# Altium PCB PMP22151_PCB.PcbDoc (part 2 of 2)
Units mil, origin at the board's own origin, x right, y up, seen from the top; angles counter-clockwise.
Board outline 3750 x 2000 mil, 2 copper layers (Top Layer, Bottom Layer), stack 62 mil thick; 80 components, 41 nets, 202 pads, 89 vias.
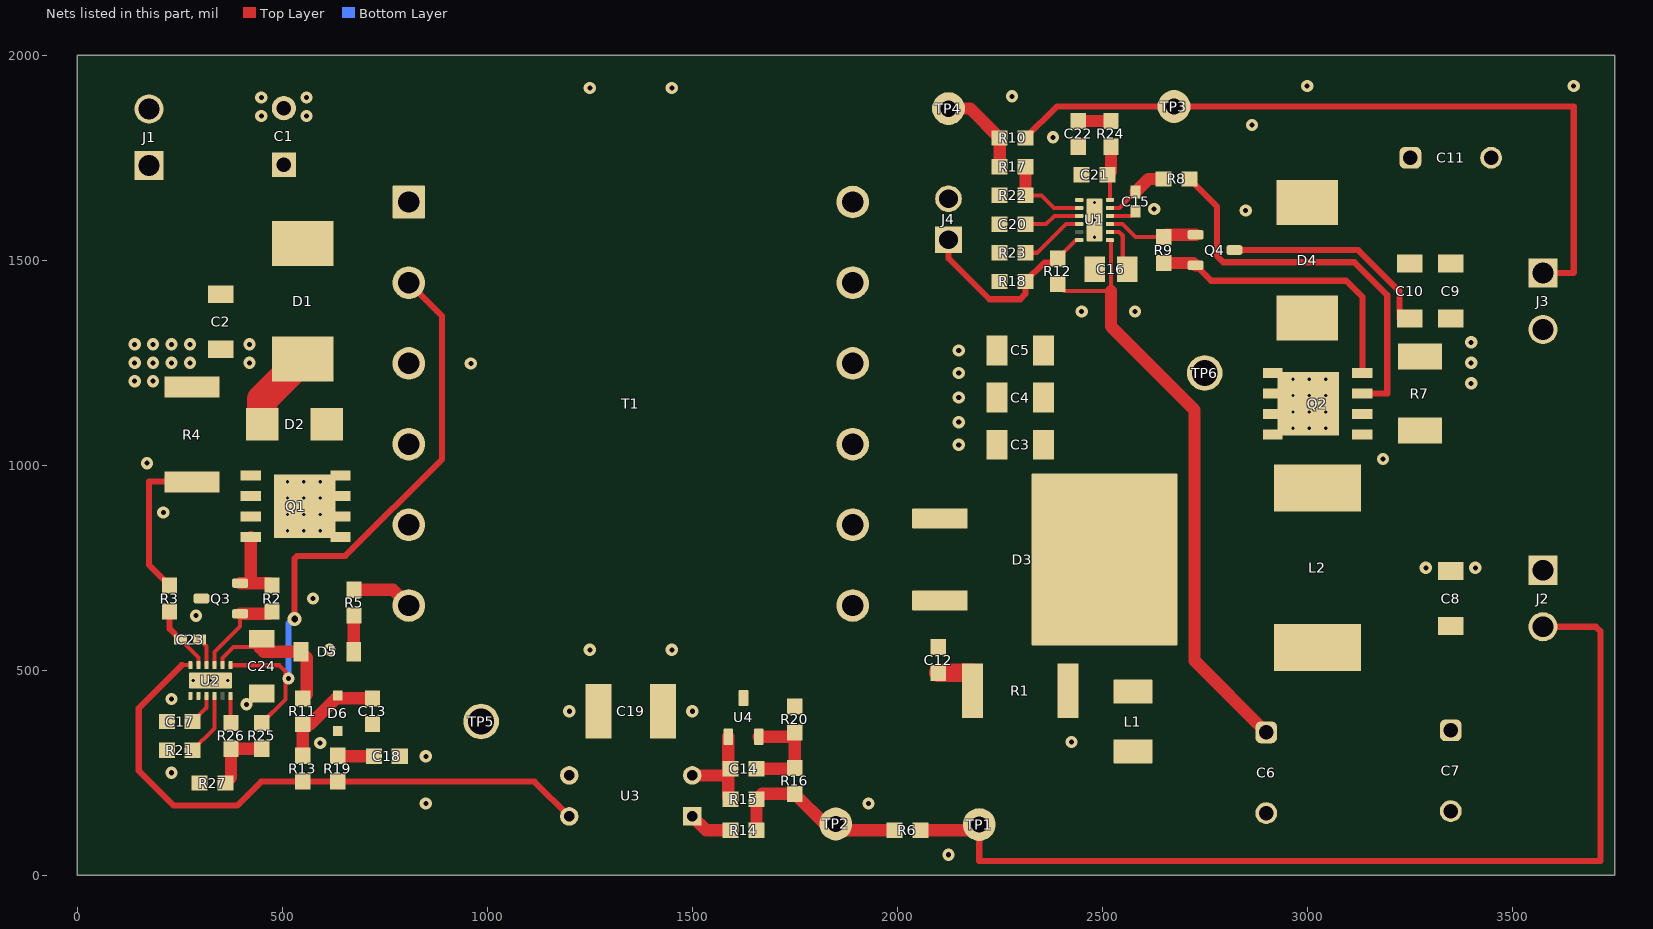
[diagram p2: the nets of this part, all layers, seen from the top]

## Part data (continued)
T1: library part CMP-0087767-1, "TRANSFORMER", Manufacturer=Wurth
TP1 TP3: library part CMP-0055137-1, "Test Point, Miniature, Red, TH", Color=Red, Manufacturer=Keystone, Supplier Part Number 1=36-5000-ND
TP2 TP4: library part CMP-0055141-1, "Test Point, Miniature, Yellow, TH", Color=Yellow, Manufacturer=Keystone, Supplier Part Number 1=36-5004-ND
TP5 TP6: library part CMP-0055148-1, "Test Point, Multipurpose, Black, TH", Color=Black, Manufacturer=Keystone, Supplier Part Number 1=36-5011-ND
U1 U2: library part CMP-0085414-1, "2.2-MHz Wide Input Nonsynchronous Boost, Sepic, Flyback Controller, DSS0012B (WSON-12)", Alternate Manufacturer="Texas Instruments", Alternate PartNumber=LM5155DSSR
U3: library part CMP-0083653-1, "Optocoupler, 5.3 kV, 100-200% CTR, SMT", Manufacturer=Vishay-Semiconductor, Supplier Part Number 1=VO618A-3-ND, Voltage_Isolation_Vrms=5.3kV
U4: library part CMP-0084732-1, "High Bandwidth Low-Iq Programmable Shunt Regulator, DBZ0003A (SOT-23-3)", Alternate Manufacturer="Texas Instruments"

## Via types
v1: diameter 29.92, hole 12.2, Top Layer to Bottom Layer, 50 vias
v2: diameter 19.68, hole 7.87, Top Layer to Bottom Layer, 30 vias
v3: diameter 29.92, hole 12.2, Top Layer to Bottom Layer, tented both sides, 8 vias
v4: diameter 34, hole 16, Top Layer to Bottom Layer, tented both sides, 1 vias

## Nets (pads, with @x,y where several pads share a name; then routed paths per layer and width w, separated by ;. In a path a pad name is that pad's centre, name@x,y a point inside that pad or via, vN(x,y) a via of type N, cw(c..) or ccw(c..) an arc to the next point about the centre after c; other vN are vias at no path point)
28V: C6.1 C7.1 C8.1 J2.2 L1.2 L2.1 R6.2 R12.2 TP1.1 U1.1 | length 3953
  Top Layer w10: R12.2@2391.3,1441.73 2408.03,1425 2521.3,1425 2521.3,1546.42 U1.1@2518.7,1549.02
  Top Layer w15: TP1.1@2200,123.74 2200,35 3715,35 3715,595 3703.9,606.1 J2.2@3575,606.1
  Top Layer w30: R6.2@2056.5,110 2186.26,110 TP1.1@2200,123.74 ; 2521.3,1425 2521.3,1338.7 2725,1135 2725,523.43 C6.1@2900,348.43
37V: C9.1 C10.1 C11.1 D4.1 J3.1 R10.2 TP3.1 | length 1849.5
  Top Layer w15: R10.2@2312.8,1798.23 2389.57,1875 TP3.1@2675,1875 3650,1875 3650,1470 3648.9,1468.9 J3.1@3575,1468.9
NetC3_1: C3.1 C4.1 C5.1 D3.2 L1.1 R1.2
NetC12_1: C12.1 R1.1 | length 127.4
  Top Layer w45: C12.1@2100,493.5 2183.86,493.5 R1.1@2183.86,450
NetC12_2: C12.2 D3.1 D3.3 T1.7 T1.8 T1.9
NetC13_2: C13.2 D6.1 R11.1 R13.2 | length 273.1
  Top Layer w30: R13.2@550,291.5 R11.1@550,368.5 568.5,368.5 631.5,431.5 C13.2@720,431.5
NetC14_1: C14.1 R16.1 R20.2 U4.2 | length 273.2
  Top Layer w30: C14.1@1656.5,260 1748.5,260 R16.1@1750,261.5 R20.2@1750,348.5 1739.25,337.76 U4.2@1662.4,337.76
NetC14_2: C14.2 R15.1 U3.2 U4.1 | length 244.2
  Top Layer w30: U3.2@1500,243.43 1584.17,243.43 1587.6,240 ; U4.1@1587.6,337.76 1587.6,240 ; R15.1@1593.5,185 1587.6,190.91 1587.6,240
NetC15_1: C15.1 R8.1 U1.5 | length 160.3
  Top Layer w10: U1.5@2518.7,1627.76 2542.2,1627.76 C15.1@2581.3,1666.85
  Top Layer w30: C15.1@2581.3,1666.85 2612.68,1698.23 R8.1@2649.8,1698.23
NetC16_1: C16.1 U1.2 | length 121.4
  Top Layer w10: U1.2@2518.7,1568.7 2541.3,1568.7 2550,1560 2550,1489.53 C16.1@2561.3,1478.23
NetC17_2: C17.2 U2.9 | length 76.5
  Top Layer w10: C17.2@281.5,375 315.16,408.66 U2.9@315.16,437.6
NetC18_2: C18.2 R19.1 | length 89.1
  Top Layer w30: R19.1@635,291.5 636.5,290 C18.2@723.5,290
NetC20_1: C20.1 U1.9 | length 139.3
  Top Layer w10: C20.1@2312.8,1588.23 2363.23,1588.23 2383.07,1608.07 U1.9@2443.9,1608.07
NetC21_1: C21.1 R24.2 U1.6 | length 135.3
  Top Layer w10: C21.1@2512.8,1708.23 2518.7,1702.32 U1.6@2518.7,1647.44
  Top Layer w30: C21.1@2512.8,1708.23 2521.3,1716.73 R24.2@2521.3,1776.73
NetC22_1: C22.1 R24.1 | length 80
  Top Layer w30: C22.1@2441.3,1839.72 R24.1@2521.3,1839.72
NetC23_1: C23.1 R3.1 U2.5 | length 160.3
  Top Layer w10: C23.1@251.38,575 295.47,530.91 U2.5@295.47,512.4
  Top Layer w15: R3.1@225,643.5 225,601.38 C23.1@251.38,575
NetD1_2: D1.2 D2.1 | length 200.4
  Top Layer w75: D2.1@451.26,1100 451.26,1160.77 D1.2@550,1259.51
NetD2_2: D2.2 Q1.5 Q1.6 Q1.7 Q1.8 Q1.9 T1.3 T1.4
  other v2: 512.5,840 552.5,840 592.5,840 512.5,880 552.5,880 592.5,880 512.5,920 552.5,920 592.5,920 512.5,960 552.5,960 592.5,960
NetD4_2: D4.2 L2.2 Q2.5 Q2.6 Q2.7 Q2.8 Q2.9
  other v2: 2965,1090 3005,1090 3045,1090 2965,1130 3005,1130 3045,1130 2965,1170 3005,1170 3045,1170 2965,1210 3005,1210 3045,1210
NetD5_2: D5.2 R5.1 | length 88.7
  Top Layer w30: D5.2@674.47,545 674.47,632.97 R5.1@675,633.5
NetJ4_1: J4.1 R12.1 R18.2 U1.12 | length 482.8
  Top Layer w10: R12.1@2391.3,1504.72 2435.59,1549.02 U1.12@2443.9,1549.02
  Top Layer w15: J4.1@2125,1550 2125,1505 2225,1405 2300,1405 2312.8,1417.8 R18.2@2312.8,1448.23 2359.45,1494.88 2381.46,1494.88 R12.1@2391.3,1504.72
NetQ1_1: Q1.1 Q1.2 Q1.3 R3.2 R4.2 | length 379.7
  Top Layer w15: R3.2@225,706.5 175,756.5 175,960 278.86,960 R4.2@280,958.86
NetQ1_4: Q1.4 Q3.2 R2.2 | length 193.6
  Top Layer w30: Q3.2@397.24,712.4 425,712.4 ; Q1.4@423,825 423,714.4 425,712.4 ; R2.2@475,706.5 469.09,712.4 425,712.4
NetQ2_1: Q2.1 Q2.2 Q2.3 R7.2 R8.2 | length 970.9
  Top Layer w15: R8.2@2712.8,1698.23 2780,1631.02 2780,1510 2795,1495 3115,1495 3195,1415 3195,1175 Q2.3@3134.5,1175
NetQ2_4: Q2.4 Q4.2 R9.2 | length 704.4
  Top Layer w15: Q4.2@2727.76,1487.6 2765.35,1450 3095,1450 3134.5,1410.5 Q2.4@3134.5,1225
  Top Layer w30: R9.2@2650,1493.5 2721.85,1493.5 Q4.2@2727.76,1487.6
NetQ3_1: Q3.1 R2.1 U2.3 | length 231.2
  Top Layer w10: U2.3@334.84,512.4 334.84,544.84 397.24,607.24 Q3.1@397.24,637.6
  Top Layer w30: Q3.1@397.24,637.6 469.09,637.6 R2.1@475,643.5
NetQ4_1: Q4.1 R9.1 U1.3 | length 224.7
  Top Layer w10: U1.3@2518.7,1588.39 2549.41,1588.39 2581.3,1556.5 R9.1@2650,1556.5
  Top Layer w30: R9.1@2650,1556.5 2655.91,1562.4 Q4.1@2727.76,1562.4
NetR5_2: R5.2 T1.6 | length 149.7
  Top Layer w30: R5.2@675,696.5 770.04,696.5 T1.6@808.66,657.87
NetR6_1: R6.1 R14.2 R15.2 R16.2 TP2.1 | length 454.3
  Top Layer w30: R14.2@1656.5,110 R15.2@1656.5,185 1670,198.5 R16.2@1750,198.5 1823.5,125 TP2.1@1850,125 1865,110 R6.1@1993.5,110
NetR10_1: R10.1 R17.2 TP4.1 | length 224.5
  Top Layer w30: TP4.1@2125,1870 2178.03,1870 R10.1@2249.8,1798.23 R17.2@2249.8,1728.23
NetR13_1: R13.1 R19.2 U2.6 U3.4 | length 1466.4
  Top Layer w10: 255,512.4 U2.6@275.79,512.4
  Top Layer w15: 255,512.4 150,407.4 150,255 235,170 390,170 448.5,228.5 R13.1@550,228.5 R19.2@635,228.5 1114.93,228.5 U3.4@1200,143.43
NetR14_1: R14.1 U3.1 | length 107.4
  Top Layer w30: U3.1@1500,143.43 1533.43,110 R14.1@1593.5,110
NetR17_1: R17.1 R22.2 U1.8 | length 213.7
  Top Layer w10: R22.2@2312.8,1658.23 2351.77,1658.23 2382.24,1627.76 U1.8@2443.9,1627.76
  Top Layer w30: R22.2@2312.8,1658.23 R17.1@2312.8,1728.23
NetR21_1: R21.1 U2.10 | length 154.7
  Top Layer w10: R21.1@281.5,305 334.84,358.35 U2.10@334.84,437.6
NetR23_2: R23.2 U1.10 | length 160.2
  Top Layer w10: R23.2@2312.8,1518.23 2341.25,1518.23 2411.41,1588.39 U1.10@2443.9,1588.39
NetR25_1: R25.1 R26.1 R27.2 | length 164.1
  Top Layer w30: R27.2@361.5,225 375,238.5 R26.1@375,308.5 R25.1@450,308.5
NetR26_2: R26.2 U2.12 | length 66.4
  Top Layer w10: U2.12@374.21,437.6 374.21,372.28 R26.2@375,371.5
PGND: C1.2 C2.2 C13.1 C17.1 C18.1 C19.2 C23.2 C24.2 D6.2 J1.2 Q3.3 R4.1 R21.2 R27.1 T1.5 TP5.1 U2.4 U2.7 U2.8 U2.13 U3.3 | length 69.4
  Top Layer w10: C23.2@298.62,575 315.16,558.46 U2.4@315.16,512.4
  other v1: 850,175 850,290 1200,400 615,550 1250,550 289.45,632.97 575,675 210,885 170,1005 140,1205 960,1248.43 140,1250 185,1250 230,1250 275,1250 140,1295 185,1295 230,1295 275,1295 449,1852 559,1852 449,1897 559,1897 1250,1920
  other v2: 282.68,475 325,475 367.32,475
  other v3: 230,250 592.56,322.7 413,417 230,430 185,1205 420.08,1250 420.08,1295
SGND: C3.2 C4.2 C5.2 C6.2 C7.2 C8.2 C9.2 C10.2 C11.2 C15.2 C16.2 C19.1 C20.2 C21.2 C22.2 J2.1 J3.2 J4.2 Q4.3 R7.1 R18.1 R20.1 R22.1 R23.1 T1.10 T1.11 T1.12 TP6.1 U1.4 U1.7 U1.13 U4.3 | length 578.5
  Top Layer w10: U1.4@2518.7,1608.07 2569.76,1608.07 C15.2@2581.3,1619.61
  Top Layer w15: Q4.3@2822.24,1525 3125,1525 3225,1425 C10.2@3225,1358.07
  other v1: 2125,50 1930,175 2425,325 1500,400 1450,550 3289.37,750 3410,750 3185,1015 2150,1050 2150,1105 2150,1165 3400,1200 2150,1225 3400,1250 2150,1280 3400,1300 2450,1375 2580,1375 2850,1621.57 2626.59,1625.2 2380,1800 2865,1830 2280,1900 1450,1920 3000,1925 3650,1925
  other v2: 2481.3,1555.91 2481.3,1598.23 2481.3,1640.55
VCC: C24.1 D5.1 R11.2 U2.2 | length 347.7
  Top Layer w10: U2.2@354.53,512.4 354.53,529.53 381.5,556.5 C24.1@443.5,556.5
  Top Layer w30: C24.1@443.5,556.5 455,545 D5.1@545.53,545 560,530.53 560,441.5 R11.2@550,431.5
Vin: C1.1 C2.1 D1.1 J1.1 R25.2 T1.1 T1.2 U2.1 | length 1514.4
  Top Layer w10: U2.1@374.21,512.4 374.21,512.13 492.87,512.13 507.5,497.5 507.5,429 R25.2@450,371.5
  Top Layer w15: v4(530,625) 530,772.2 536.63,778.83 653.83,778.83 890,1015 890,1363.94 T1.2@808.66,1445.28
  Bottom Layer w15: v3(515,480) 515,613.37 526.63,625 v4(530,625)
pads on no net: U1.11 U2.11

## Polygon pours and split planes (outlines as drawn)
NetD2_2 on Top Layer "TOP_LAYER_NETD2_2_P002" (solid, remove dead copper, pour order 2): 475,810 475,980 565,1070 565,1325 875,1325 875,950 805,950 665,810
SGND on Top Layer "TOP_LAYER_SGND_P026" (solid, remove dead copper, pour order 26): 1400,0 1400,2000 3750,2000 3750,0
37V on Top Layer "TOP_LAYER_37V_P024" (solid, remove dead copper, pour order 24): 2900,1549.02 2900.98,1550 3130,1550 3255,1425 3625,1425 3625,1850 2900,1850
NetD4_2 on Top Layer "TOP_LAYER_NETD4_2_P022" (solid, remove dead copper, pour order 22): 3150,875 2875,875 2875,1425 3090,1425 3090,1050 3150,1050
NetQ2_1 on Top Layer "TOP_LAYER_NETQ2_1_P020" (solid, remove dead copper, pour order 20): 3100,1200 3350,1200 3350,1050 3100,1050
28V on Top Layer "TOP_LAYER_28V_P018" (solid, remove dead copper, pour order 18): 2475,200 3625,200 3625,675 2475,675
NetC3_1 on Top Layer "TOP_LAYER_NETC3_1_P016" (solid, remove dead copper, pour order 16): 2325,1325 2325,375 2700,375 2700,1125 2500,1325
NetC12_2 on Top Layer "TOP_LAYER_NETC12_2_P014" (solid, remove dead copper, pour order 14): 1840,1100 1840,635 1937.29,537.71 2200,537.71 2200,870 1970,1100
PGND on Top Layer "TOP_LAYER_PGND_P006" (solid, remove dead copper, pour order 6): 1300,0 1300,2000 0,2000 0,0
Vin on Top Layer "TOP_LAYER_VIN_P004" (solid, remove dead copper, pour order 4): 125,1800 950,1800 950,1325 125,1325
NetQ1_1 on Top Layer "TOP_LAYER_NETQ1_1_P000" (solid, remove dead copper, pour order 0): 455,1050 455,855 280,855 205,930 205,1050
SGND on Bottom Layer "BOTTOM_LAYER_SGND_P012" (solid, remove dead copper, pour order 12): 1400,0 1400,2000 3750,2000 3750,0
PGND on Bottom Layer "BOTTOM_LAYER_PGND_P010" (solid, remove dead copper, pour order 10): 1300,0 1300,2000 0,2000 0,0

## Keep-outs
Keep-Out Layer:
  text ".Layer_Name" at 577,-858.49 h60

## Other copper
Top Layer:
  region net NetR13_1: 255,520 276,520 276,503 237,503
  text ".Layer_Name" at 577,-858.49 h60
Bottom Layer:
  text ".Layer_Name" at 577,-858.49 h60

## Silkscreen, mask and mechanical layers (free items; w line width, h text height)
Top Overlay:
  lines w10: 2785,475 2815,475 ; 2800,460 2800,490 ; 3085,1775 3115,1775 ; 3100,1760 3100,1790 ; 3235,475 3265,475 ; 3250,460 3250,490 ; 100,455 180,455 180,520 100,520 100,455 ; 1825,355 1825,420 1905,420 1905,355 1825,355 ; 2625,1355 2625,1420 2705,1420 2705,1355 2625,1355
  text "'.PRJ_Number'.PCB_Rev" at 70,80 h108.27
  text ".Layer_Name" at 577,-858.49 h60
Bottom Overlay:
  text ".Layer_Name" at 577,-858.49 h60
Top Paste:
  text ".Layer_Name" at 577,-858.49 h60
Bottom Paste:
  text ".Layer_Name" at 577,-858.49 h60
Top Solder:
  text ".Layer_Name" at 577,-858.49 h60
  text ".Layer_Name" at 577,-858.49 h60
Bottom Solder:
  text ".Layer_Name" at 577,-858.49 h60
Drill Guide:
  text ".Layer_Name" at 577,-858.49 h60
M1 Board Outline:
  the board outline again, w10
  text ".Layer_Name" at 577,-858.49 h60
M2 Board Dimensions:
  rectangle: 0,-275 125,-150
  rectangle: 125,-400 500,-275
  lines w7: 0,-275 1000,-275 ; 125,-400 125,-150 ; 250,-400 250,-150 ; 500,-400 500,-150 ; 750,-400 750,-150 ; 0,-400 1000,-400 1000,-150 0,-150 0,-400
  text ".Layer_Name" at 577,-858.49 h60
M3 3D STEP Top:
  text ".Layer_Name" at 577,-858.49 h60
M4 3D STEP Bottom:
  text ".Layer_Name" at 577,-858.49 h60
M5 Assembly Top:
  lines w10: -292,-930.17 6308,-930.17 ; -292,-726.83 6310,-726.83 ; -292,-523.5 -292,-1133.5 3713,-1133.5 6310,-1133.5 6310,-523.5 -291.5,-523.5 -291.5,-1133.5 1284,-1133.5 ; 2173,-1133.5 2173,-523.5 ; 3440,-726.83 3440,-523.5 ; 4280,-726.83 4280,-523.5 ; 4902,-1140 4902,-937.17
  text "COMPONENTS MARKED 'DNP' SHOULD NOT BE POPULATED." at 1153.5,-318.5 h60
  text "ASSEMBLY VARIANT:" at 1153,-434 h60
  text ".VariantName" at 2189,-434 h60
  text "PCB VIEWED FROM TOP SIDE" at -228.5,-655.67 h60
  text "BOARD #:" at 2248,-655.67 h60
  text ".PRJ_Number" at 2793.5,-655.67 h60
  text "REV:" at 3638,-655.67 h60
  text ".PCB_Rev" at 3929.5,-655.67 h60
  text "SVN REV:" at 4476,-655.67 h60
  text ".VersionControl_RevNumber" at 4982,-655.67 h60
  text "TID #:" at 2248,-859 h60
  text ".TID" at 2793.5,-859 h60
  text "PLOT NAME =" at -228.5,-1064.34 h60
  text ".plot_File_Name" at 577,-1064.34 h60
  text "GENERATED    :" at 2250,-1064.34 h60
  text ".Print_Date" at 3119.5,-1064.34 h60
  text ".Print_Time" at 3848.5,-1064.34 h60
  text "TEXAS INSTRUMENTS" at 5113,-1064.34 h60
M6 Assembly Bottom:
  lines w10: -292.5,-727.33 6309.5,-727.33 ; -290.5,-930.67 6309.5,-930.67 ; 1115.5,-1140.5 1115.5,-937.67 ; 1737.5,-727.33 1737.5,-524 ; 2577.5,-727.33 2577.5,-524 ; 3844.5,-1134 3844.5,-524 ; 4733.5,-1134 6309,-1134 6309,-524 -292.5,-524 -292.5,-1134 2304.5,-1134 6309.5,-1134 6309.5,-524
  text "COMPONENTS MARKED 'DNP' SHOULD NOT BE POPULATED." at 6102,-318 h60
  text ".VariantName" at 5058,-434 h60
  text "ASSEMBLY VARIANT:" at 6097,-434 h60
  text ".VersionControl_RevNumber" at 1035.5,-656.17 h60
  text "SVN REV:" at 1541.5,-656.17 h60
  text ".PCB_Rev" at 2088,-656.17 h60
  text "REV:" at 2379.5,-656.17 h60
  text ".PRJ_Number" at 3224,-656.17 h60
  text "BOARD #:" at 3769.5,-656.17 h60
  text "PCB VIEWED FROM BOTTOM SIDE" at 6246,-656.17 h60
  text ".TID" at 3224,-859.5 h60
  text "TID #:" at 3769.5,-859.5 h60
  text "TEXAS INSTRUMENTS" at 904.5,-1064.84 h60
  text ".Print_Time" at 2169,-1064.84 h60
  text ".Print_Date" at 2898,-1064.84 h60
  text "GENERATED    :" at 3767.5,-1064.84 h60
  text ".plot_File_Name" at 5440.5,-1064.84 h60
  text "PLOT NAME =" at 6246,-1064.84 h60
M9 Title Sheet:
  drawing of 57 lines, arcs and shapes, not listed
  text "1" at 739.84,8036.5 h70
  text "2" at 3235.5,8036.5 h70
  text "3" at 5724.84,8036.5 h70
  text "4" at 8231.51,8036.5 h70
  text "5" at 10730.5,8036.5 h70
  text "6" at 13235.5,8036.5 h70
  text "A" at -416.5,6893.5 h70
  text "A" at 14383.5,6893.5 h70
  text "B" at -416.5,4513.5 h70
  text "B" at 14383.5,4513.5 h70
  text "C" at -416.5,2138.5 h70
  text "C" at 14383.5,2138.5 h70
  text "PROJECT TITLE:" at 11343.5,277.5 h45
  text ".PRJ_Title" at 11393.5,144.17 h70
  text "DESIGNED FOR:" at 11343.5,-23.5 h45
  text ".PRJ_Customer" at 11393.5,-163.5 h70
  text "D" at -416.5,-231.5 h70
  text "D" at 14383.5,-231.5 h70
  text "FILE NAME:" at 11343.5,-323.5 h45
  text ".PCB_File_Name_No_Path" at 11393.5,-443.5 h70
  text "Texas Instruments (TI) and/or its licensors do not warrant the accuracy or completeness of this specification" at 6374,-605.34 h45
  text "ENGINEER:" at 11343.5,-613.5 h45
  text "LAYOUT BY:" at 12848.5,-613.5 h45
  text "or any information contained therein. TI and/or its licensors do not warrant that this design will meet" at 6329.01,-718 h45
  text ".PRJ_Engineer" at 11393.5,-768.49 h70
  text ".PCB_Layout" at 12899,-768.49 h70
  text "the specifications, will be suitable for your application or fit for any particular purpose, or will operate in" at 6329.01,-830.67 h45
  text ".Layer_Name" at 577,-858.49 h60
  text "ALTIUM DESIGNER VERSION:" at 12848.5,-923.5 h45
  text "an implementation. TI and/or its licensors do not warrant that the design is production worthy. You should" at 6329.01,-943.33 h45
  text "completely validate and test your design implementation to confirm the system functionality for your application." at 6374,-1056 h45
  text ".print_Scale" at 11393.5,-1056.83 h70
  text ".Application_BuildNumber" at 12899,-1056.83 h70
  text "1" at 739.84,-1263.5 h70
  text "2" at 3235.5,-1263.5 h70
  text "3" at 5724.84,-1263.5 h70
  text "4" at 8231.51,-1263.5 h70
  text "5" at 10730.5,-1263.5 h70
  text "6" at 13235.5,-1263.5 h70
M10 Fab Notes:
  drawing of 189 lines, arcs and shapes, not listed
  text "DESIGN INFORMATION" at 12382.02,6356.17 h60
  text "MIN. TRACK WIDTH:" at 11737.46,6224.05 h60
  text "8" at 12833.7,6224.05 h60
  text "MIL" at 12988.46,6224.05 h60
  text "MIN. CLEARANCE:" at 11737.46,6099.92 h60
  text "0.2" at 12773.7,6099.93 h60
  text "mm" at 12988.46,6099.92 h60
  text "MIN. VIA PAD SIZE:" at 11737.46,5975.8 h60
  text "24" at 12803.71,5975.8 h60
  text "MIL" at 12988.46,5975.8 h60
  text "0.05mm (2MIL)" at 12432.46,5845.9 h60
  text "MINIMUM ANNULAR RING" at 11408.23,5837.67 h60
  text "EXTERNAL" at 13140.46,5837.67 h60
  text "PER" at 11608.23,5727.55 h60
  text "IPC-D-275 CLASS 2 LEVEL C" at 11828.23,5727.54 h60
  text "MIL, HOLES" at 13316.46,5627.07 h60
  text "+/-" at 12924,5618.48 h60
  text "+/-" at 13778,5618.48 h60
  text "REGISTRATION TOLERANCES:" at 11408.23,5617.42 h60
  text "METAL" at 12608,5617.42 h60
  text "5" at 13184.2,5617.42 h60
  text "3" at 14017.2,5617.42 h60
  text "MIL" at 14133.46,5617.42 h60
  text "HOLE SIZE TOLERANCE (UNLESS OTHERWISE SPECIFIED):" at 11408.23,5519.1 h60
  text "+/-" at 13778,5516.23 h60
  text "3" at 14017.2,5515.17 h60
  text "MIL" at 14133.46,5515.17 h60
  text "MATERIAL:" at 11333.46,5377.52 h60
  text "FR-4 High Tg" at 12319.9,5249 h60
  text "X" at 12175.46,5241.01 h60
  text "FR-408" at 11754.46,5236.49 h60
  text "OTHER" at 13242.46,5236.49 h60
  text "62 MIL (1.6mm) +/-10%" at 12074.56,5093.46 h60
  text "X" at 11954.46,5091.01 h60
  text "THICKNESS:" at 11408.23,5085.24 h60
  text "OTHER" at 13359.46,5085.24 h60
  text "TOLERANCE:" at 11408.23,4946.92 h60
  text "X" at 12256.46,4946.92 h60
  text "ANSI IPC-6012 TYPE 3 CLASS 2" at 12434.48,4946.92 h60
  text "OTHER +/-" at 12434.46,4802.73 h60
  text "BOW & TWIST:" at 11408.23,4657.54 h60
  text "X" at 12256.46,4657.54 h60
  text "ANSI IPC-6012 TYPE 3 CLASS 2" at 12434.48,4657.54 h60
  text "OTHER +/-" at 12434.46,4510.85 h60
  text "DRILLING:" at 11333.46,4380.23 h60
  text "NC_DRILL FILES" at 13094.46,4275.04 h60
  text "REFERENCE:" at 11408.23,4271.1 h60
  text "X" at 12065.46,4271.01 h60
  text "AS SHOWN" at 12243.46,4271.1 h60
  text "X" at 12966.46,4271.1 h60
  text "OTHER" at 13392.46,4128.85 h60
  text "PTH COPPER THICKNESS:" at 11407.91,4125.32 h60
  text "X" at 12547.14,4125.32 h60
  text "20-30 um" at 12675.14,4125.32 h60
  text "BOARD FINISH:" at 11333.46,3977.73 h60
  text "SILKSCREEN:" at 11488.68,3867.6 h60
  text "X" at 12446.46,3867.6 h60
  text "TOP" at 12563.46,3867.6 h60
  text "X" at 12956.46,3867.6 h60
  text "BOTTOM" at 13074.46,3867.6 h60
  text "SILKSCREEN COLOR:" at 11488.68,3712.41 h60
  text "X" at 12445.46,3712.41 h60
  text "WHITE" at 12563.46,3712.41 h60
  text "OTHER" at 13074.46,3712.41 h60
  text "X" at 12576.46,3568.96 h60
  text "GREEN" at 12694.46,3568.96 h60
  text "OTHER" at 13312.46,3568.96 h60
  text "SOLDER RESIST COLOR:" at 11488.68,3562.1 h60
  text "X" at 12576.46,3414.71 h60
  text "MATTE" at 12694.46,3414.71 h60
  text "SEMI-GLOSS" at 13312,3414.07 h60
  text "IMMERSION GOLD (ENIG)" at 12394.46,3241.94 h60
  text "ENEPIG" at 13732,3234.72 h60
  text "SURFACE FINISH:" at 11333.46,3233.72 h60
  text "X" at 12216.46,3233.72 h60
  text "IMM. TIN/SILVER OR EQUIV" at 11663,3096.4 h60
  text "OTHER" at 13094.46,3092.47 h60
  text "ARRAY/PANEL:" at 11333.46,2937.09 h60
  text "CUT AND TRIM PER M1 BOARD OUTLINE" at 12394.46,2928.87 h60
  text "N.C. ROUTE" at 12394.46,2792.9 h60
  text "X" at 13082.46,2792.9 h60
  text "V. SCORE" at 13260.46,2792.9 h60
  text "CERTIFICATION:" at 11333.46,2663.77 h60
  text "MATERIALS AND WORKMANSHIP FOR ALL PCBS" at 12058.46,2663.77 h60
  text "TO MEET OR EXCEED THE REQUIREMENTS OF:" at 12058.46,2569.71 h60
  text "X" at 11695.97,2441.08 h60
  text "ANSI IPC-A-600F CLASS ->" at 11823.96,2441.08 h60
  text "X" at 13471.97,2441.08 h60
  text "2" at 13581.96,2441.08 h60
  text "1" at 13266.96,2439.58 h60
  text "3" at 13935.96,2439.58 h60
  text "X" at 12507.97,2293.39 h60
  text "RoHS" at 12635.96,2293.39 h60
  text "OTHER" at 13280.36,2293.39 h60
  text "PER ORDER" at 13677.42,2293.39 h60
  text "ALL BOARDS MUST MEET OR EXCEED UL94-V0 REQUIREMENTS." at 11361,2139.57 h60
  text "PCB MUST BEAR THE UL94V-0 UL REGISTERED MATERIAL ID NUMBER" at 11361,2023.5 h60
  text "ADDITIONAL REQUIREMENTS:" at 11333.46,1854.08 h60
  text "MICROSECTION:" at 11408.23,1746.95 h60
  text "YES" at 12313.96,1746.95 h60
  text "REQUIRED" at 13175.46,1602.62 h60
  text "BARE BOARD ELEC. TEST:" at 11408.23,1599.76 h60
  text "NONE" at 12713.96,1599.76 h60
  text "X" at 13057.46,1599.76 h60
  text "PER ORDER" at 13767.46,1599.76 h60
  text "XX MIL VIAS REQUIRE NON-CONDUCTIVE FILL AND PLANARIZE" at 11576.38,1394.82 h59
  text "XX MIL VIAS REQUIRE CONDUCTIVE FILL AND PLANARIZE" at 11584.38,1290.84 h60
  text "OUTER XX MIL TRACES REQUIRE 50 OHM SINGLE-ENDED IMPEDANCE" at 11583.39,1127.46 h58
  text "LAYER 2 & 3 (INNER LAYERS) XX MIL WIDE, XX MIL SPACE / TRACES REQUIRE 100 OHM DIFFERENTIAL IMPEDANCE" at 11575.39,891.74 h60
  text ".Layer_Name" at 577,-858.49 h60
M11 Gerber Information:
  lines w10: -292,-930.17 6308,-930.17 ; -292,-726.83 6310,-726.83 ; -292,-523.5 -292,-1133.5 3713,-1133.5 6310,-1133.5 6310,-523.5 -291.5,-523.5 -291.5,-1133.5 1284,-1133.5 ; 2173,-1133.5 2173,-523.5 ; 3440,-726.83 3440,-523.5 ; 4280,-726.83 4280,-523.5 ; 4902,-1140 4902,-937.17
  text "ALL ARTWORK VIEWED FROM TOP SIDE" at -228.5,-655.67 h60
  text "BOARD #:" at 2248,-655.67 h60
  text ".PRJ_Number" at 2793.5,-655.67 h60
  text "REV:" at 3638,-655.67 h60
  text ".PCB_Rev" at 3929.5,-655.67 h60
  text "SVN REV:" at 4476,-655.67 h60
  text ".VersionControl_RevNumber" at 4982,-655.67 h60
  text "LAYER NAME =" at -228.5,-858.49 h60
  text "TID #:" at 2248,-859 h60
  text ".TID" at 2793.5,-859 h60
  text "PLOT NAME =" at -228.5,-1064.34 h60
  text ".plot_File_Name" at 577,-1064.34 h60
  text "GENERATED    :" at 2250,-1064.34 h60
  text ".Print_Date" at 3119.5,-1064.34 h60
  text ".Print_Time" at 3848.5,-1064.34 h60
  text "TEXAS INSTRUMENTS" at 5113,-1064.34 h60
M12 Stackup:
  drawing of 191 lines, arcs and shapes, not listed
  text "Layer" at 9797.84,7537.5 h60
  text "Name" at 10207.76,7537.5 h60
  text "Material" at 11137.5,7537.5 h60
  text "Thickness" at 11997.27,7537.5 h60
  text "Constant" at 12647.1,7537.5 h60
  text "Board Layer Stack" at 13216.96,7537.5 h60
  text "1" at 9797.84,7417.5 h60
  text "Top Overlay" at 10207.76,7417.5 h60
  text "2" at 9797.84,7297.5 h60
  text "Top Solder" at 10207.76,7297.5 h60
  text "Solder Resist" at 11137.5,7297.5 h60
  text "0.40mil" at 11997.27,7297.5 h60
  text "3.5" at 12647.1,7297.5 h60
  text "3" at 9797.84,7177.5 h60
  text "Top Layer" at 10207.76,7177.5 h60
  text "Copper" at 11137.5,7177.5 h60
  text "1.40mil" at 11997.27,7177.5 h60
  text "4" at 9797.84,7057.5 h60
  text "Dielectric1" at 10207.76,7057.5 h60
  text "FR-4" at 11137.5,7057.5 h60
  text "59.20mil" at 11997.27,7057.5 h60
  text "4.8" at 12647.1,7057.5 h60
  text "5" at 9797.84,6937.5 h60
  text "Bottom Layer" at 10207.76,6937.5 h60
  text "Copper" at 11137.5,6937.5 h60
  text "1.40mil" at 11997.27,6937.5 h60
  text "6" at 9797.84,6817.5 h60
  text "Bottom Solder" at 10207.76,6817.5 h60
  text "Solder Resist" at 11137.5,6817.5 h60
  text "0.40mil" at 11997.27,6817.5 h60
  text "3.5" at 12647.1,6817.5 h60
  text "7" at 9797.84,6697.5 h60
  text "Bottom Overlay" at 10207.76,6697.5 h60
  text ".Layer_Name" at 577,-858.49 h60
M13 Component Bodies Top:
  text ".Layer_Name" at 577,-858.49 h60
M14 Component Bodies Bottom:
  text ".Layer_Name" at 577,-858.49 h60
M15 Courtyards Top:
  text ".Layer_Name" at 577,-858.49 h60
M16 Courtyards Bottom:
  text ".Layer_Name" at 577,-858.49 h60
Drill Drawing:
  text ".Layer_Name" at 577,-858.49 h60
M17 Embedded Cavity:
  text ".Layer_Name" at 577,-858.49 h60
M18 Embedded Assembly:
  text ".Layer_Name" at 577,-858.49 h60
M19 Embedded Keepout:
  text ".Layer_Name" at 577,-858.49 h60

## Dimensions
0,-400 to 1000,-400 on M2 Board Dimensions
0,0 to 0,2000 on M2 Board Dimensions
0,0 to 3750,0 on M2 Board Dimensions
